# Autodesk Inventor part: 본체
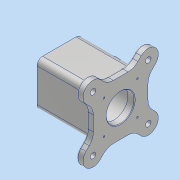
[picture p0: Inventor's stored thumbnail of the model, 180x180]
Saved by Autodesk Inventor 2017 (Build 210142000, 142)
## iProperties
Part Number: 본체
Material: 알루미늄 6061
Document SubType Name: Modeling
Designer: MRC
Mass: 1072.96 g
Surface Area: 880.2 cm^2
Volume: 397.391 cm^3
Density: 2.7 g/cm^3
Appearance: 알루미늄 - 평지
Author: MRC
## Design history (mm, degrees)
sketch "스케치1"
  geometry: L1 (-49, 40)-(61, 40); L2 (61, 40)-(61, -40); L3 (61, -40)-(-49, -40); L4 (-49, -40)-(-49, 40); 2 further points
  constraints: 8 end point, 2 parallel, 1 horizontal, 1 horizontal alignment, 1 midpoint, 1 perpendicular
  dimensions: "d0" = 110 distance of L1.start L1.end; "d1" = 61 distance from line of point (0, 0) L2; "d2" = 80 distance of L3.end L1.start
extrude "돌출1" new body sketch "스케치1" stored distance "d3" = 80; taper "d4" = 0 deg
fillet "모깎기1" dims "d5" = 10
sketch "스케치2"
  geometry: C1 r 25 at (40, 30); 1 further point
  constraints: 1 centre point, 1 coincident
  dimensions: "d6" = 50 diameter of C1
extrude "돌출2" cut sketch "스케치2" distance "d7" = 12; taper "d8" = 0 deg
sketch "스케치3"
  geometry: C1 r 25 at (40, 30); 1 further point
  constraints: 1 centre point, 1 coincident
  dimensions: "d9" = 50 diameter of C1
extrude "돌출3" cut sketch "스케치3" distance "d10" = 12; taper "d11" = 0 deg
sketch "스케치4"
  geometry: C1 r 25 at (0, 0) reference; C2 r 35 at (0, 0)
  constraints: 1 centre point, 1 coincident
  dimensions: "d12" = 70 diameter of C2
extrude "돌출4" cut sketch "스케치4" distance "d13" = 86; taper "d14" = 0 deg
sketch "스케치5"
  geometry: L1 (10, 0)-(70, 0); L2 (70, 0)-(70, 60); L3 (70, 60)-(10, 60); L4 (10, 60)-(10, 0); L5 (10, 0)-(70, 60); L6 (70, 0)-(10, 60); C1 r 25 at (40, 30) reference; A1 r 10 centre (70, 60) between (80, 60) and (70, 70) reference; 4 further points
  constraints: 12 end point, 4 coincident, 2 midpoint, 2 parallel, 1 horizontal, 1 perpendicular
  dimensions: "d15" = 60 distance of L2.end L1.end (derived)
hole "구멍1" sketch "스케치5" at (10, 60), (70, 60), (70, 0), (10, 0) diameter "d16" = 3.242; stored, may be unused: countersink angle "d20" = 90 deg, drill point angle "d22" = 118 deg; dims "d17" = 8, "d18" = 4, "d19" = 2, "d21" = 10
node "작업 평면1"
sketch "스케치6"
  geometry: L1 (-9.497, 79.497)-(89.497, -19.497); L2 (89.497, 79.497)-(-9.497, -19.497); L3 (40, 30)-(40, 100); L4 (-9, -19)-(89, -19); L5 (89, -19)-(89, 79); L6 (89, 79)-(-9, 79); L7 (-9, 79)-(-9, -19); L8 (-9, -19)-(89, 79); L9 (89, -19)-(-9, 79); L10 (76.77, 92.225)-(63.544, 79); L11 (102.225, 66.77)-(89, 53.544); C1 r 1.621 at (10, 0) reference; C2 r 1.621 at (70, 60) reference; C3 r 1.621 at (10, 60) reference; C4 r 1.621 at (70, 0) reference; C5 r 25 at (40, 30) reference; C6 r 18 at (-9.497, 79.497); C7 r 18 at (89.497, -19.497); C8 r 18 at (-9.497, -19.497); A1 r 70 centre (40, 30) between (-9.497, 79.497) and (89.497, 79.497); A2 r 18 centre (89.497, 79.497) between (76.77, 92.225) and (102.225, 66.77); 1 further point
  constraints: 22 end point, 7 point on circle, 5 centre point, 4 midpoint, 4 parallel, 3 coincident, 2 point on line, 2 tangent, 1 horizontal, 1 perpendicular, 1 vertical
  dimensions: "d23" = 140 diameter of A1; "d24" = 36 diameter of C6; "d25" = 36 diameter of A2; "d26" = 36 diameter of C7; "d27" = 36 diameter of C8; "d29" = 45 deg angle of L3 L2; "d30" = 45 deg angle of L3 L1; "d31" = 98 distance of L6.end L5.end; "d32" = 98 distance of L5.end L4.end
extrude "돌출5" join sketch "스케치6" distance "d49" = 12; taper "d50" = 0 deg
fillet "모깎기5" dims "d82" = 25
sketch "스케치7"
  geometry: C1 r 20 at (49, 30); 1 further point
  constraints: 1 centre point, 1 coincident
  dimensions: "d51" = 40 diameter of C1
extrude "돌출6" join sketch "스케치7" distance "d52" = 15; taper "d53" = 0 deg
hole "구멍2" diameter "d56" = 25; stored, may be unused: countersink angle "d60" = 90 deg, drill point angle "d62" = 0 deg; dims "d54" = 10, "d55" = 10, "d57" = 8, "d58" = 30, "d59" = 8, "d61" = 10
chamfer "모따기1" distance "d63" = 1; stored, may be unused: second distance "d64" = 2, angle "d65" = 45 deg
fillet "모깎기2" dims "d66" = 3
sketch "스케치8"
  geometry: A1 r 15 centre (-89.497, 79.497) between (-78.891, 90.104) and (-100.104, 68.891) reference; A2 r 15 centre (-89.497, -19.497) between (-100.104, -8.891) and (-78.891, -30.104) reference; A3 r 15 centre (9.497, -19.497) between (-1.109, -30.104) and (20.104, -8.891) reference; A4 r 15 centre (9.497, 79.497) between (20.104, 68.891) and (-1.109, 90.104) reference; 13 further points
  constraints: 4 coincident
hole "구멍3" sketch "스케치8" at (-89.497, 79.497), (-89.497, -19.497), (9.497, -19.497), (9.497, 79.497) diameter "d67" = 10; stored, may be unused: countersink angle "d71" = 90 deg, drill point angle "d73" = 0 deg; dims "d68" = 8, "d69" = 18, "d70" = 4, "d72" = 10
fillet "모깎기3" dims "d74" = 3
sketch "스케치9"
  geometry: L1 (0, 60)-(0, 0) reference; C1 r 20 at (49, 30) reference; 1 further point
  constraints: 1 horizontal alignment, 1 other
  dimensions: "d75" = 10 distance from line of L1 point (10, 30)
feature "엠보싱1" sketch "스케치9" dims "d0" = 110, "d1" = 61, "d2" = 80, "d76" = 0.5, "d77" = 0
fillet "모깎기4" dims "d78" = 3
node "솔리드1"
mirror "미러1"
pattern_circular "원형 패턴1" dims angle "d80" = 360 deg
pattern_circular "원형 패턴2" dims angle "d84" = 360 deg
